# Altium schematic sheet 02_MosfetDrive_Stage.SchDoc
size A4; SheetNumber: 2; SheetTotal: 3
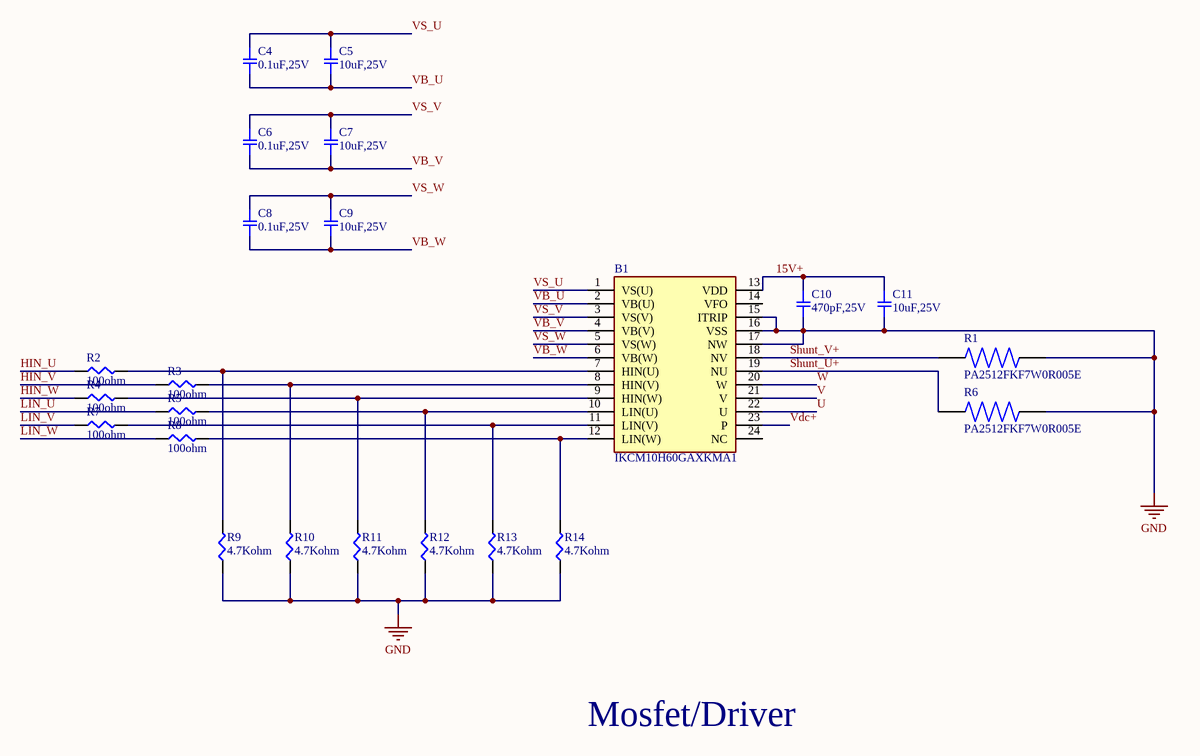
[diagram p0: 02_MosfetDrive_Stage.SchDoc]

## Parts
B1  IKCM10H60GAXKMA1  [997_IKCM10H60GAXKMA1]
C4  0.1uF,25V  [001_SMD-1206]
C5  10uF,25V  [001_SMD-1206]
C6  0.1uF,25V  [001_SMD-1206]
C7  10uF,25V  [001_SMD-1206]
C8  0.1uF,25V  [001_SMD-1206]
C9  10uF,25V  [001_SMD-1206]
C10  470pF,25V  [006_SMD_0605]
C11  10uF,25V  [006_SMD_0605]
R1  PA2512FKF7W0R005E  [097_PA2512FKF7W0R005E]
R2  100ohm  [001_SMD-1206]
R3  100ohm  [001_SMD-1206]
R4  100ohm  [001_SMD-1206]
R5  100ohm  [001_SMD-1206]
R6  PA2512FKF7W0R005E  [097_PA2512FKF7W0R005E]
R7  100ohm  [001_SMD-1206]
R8  100ohm  [001_SMD-1206]
R9  4.7Kohm  [001_SMD-1206]
R10  4.7Kohm  [001_SMD-1206]
R11  4.7Kohm  [001_SMD-1206]
R12  4.7Kohm  [001_SMD-1206]
R13  4.7Kohm  [001_SMD-1206]
R14  4.7Kohm  [001_SMD-1206]

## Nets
GND: B1.15(ITRIP) B1.16(VSS) B1.17(NW) C10.2 C11.2 R1.2 R6.2 R9.1 R10.1 R11.1 R12.1 R13.1 R14.1
15V+: B1.13(VDD) C10.1 C11.1
HIN_U: R2.1
HIN_V: R3.1
HIN_W: R4.1
LIN_U: R5.1
LIN_V: R7.1
LIN_W: R8.1
Shunt_U+: B1.19(NU) R6.1
Shunt_V+: B1.18(NV) R1.1
U: B1.22(U)
V: B1.21(V)
VB_U: B1.2(VB(U)) C4.2 C5.2
VB_V: B1.4(VB(V)) C6.2 C7.2
VB_W: B1.6(VB(W)) C8.2 C9.2
Vdc+: B1.23(P)
VS_U: B1.1(VS(U)) C4.1 C5.1
VS_V: B1.3(VS(V)) C6.1 C7.1
VS_W: B1.5(VS(W)) C8.1 C9.1
W: B1.20(W)
NetB1_7: B1.7(HIN(U)) R2.2 R9.2
NetB1_8: B1.8(HIN(V)) R3.2 R10.2
NetB1_9: B1.9(HIN(W)) R4.2 R11.2
NetB1_10: B1.10(LIN(U)) R5.2 R12.2
NetB1_11: B1.11(LIN(V)) R7.2 R13.2
NetB1_12: B1.12(LIN(W)) R8.2 R14.2

Not connected (* = marked no-connect by the designer): B1 14(VFO) 24(NC)

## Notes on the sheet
- Mosfet/Driver

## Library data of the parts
B1 = IKCM10H60GAXKMA1: Intelligent Power Module 3-Ph 600V 10A; Manufacturer_Name: Infineon; Geometry.Height: 5.6mm
C4-C9 = C_1206_Template: CAP CER 1206; Part Number: GC321AD72E103KX01D; Manufacturer: Murata Electronics North America; Factory Stock: 0; Unit Price (USD): 0.3; Minimum Quantity: 1; Value: 10000pF; Tolerance: ±10%; Voltage: 250V; Temperature Coefficient: X7T
C10 C11 = C_0605_Template: CAP CER 0605; Part Number: GC321AD72E103KX01D; Manufacturer: Murata Electronics North America; Factory Stock: 0; Unit Price (USD): 0.3; Minimum Quantity: 1; Value: 10000pF; Tolerance: ±10%; Voltage: 250V; Temperature Coefficient: X7T
R1 R6 = PA2512FKF7W0R005E: 5 mΩ, 2 W, ±1% current-sense shunt resistor, 2512 (6332 metric) SMD package, low-resistance metal-element construction.; MF: Bourns; MP: CRF2512-FZ-R005ELF
R2-R5 R7-R14 = R_1206_Template: RES SMD 1206; Part Number: ERJ-8BQF1R0V; Manufacturer: Panasonic Electronic Components; Factory Stock: 0; Unit Price (USD): 0.05778; @ qty: 1500; Minimum Quantity: 1; Value: 1; Tolerance: ±1%; Power (Watts): 0.5W, 1/2W; Temperature Coefficient: ±200ppm/°C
